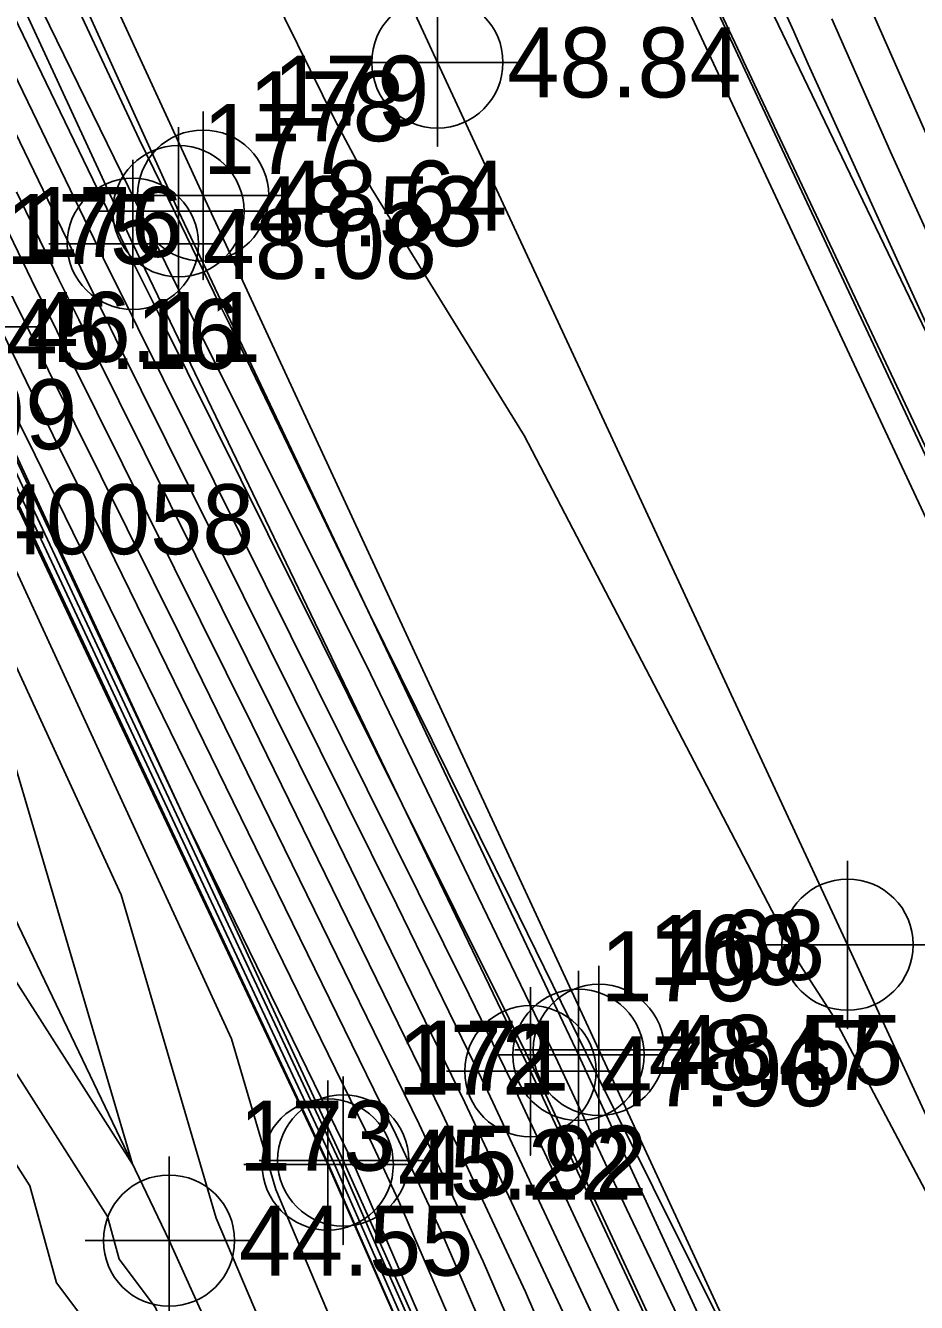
# Model space of a CAD drawing. Extents: x 2090860 to 2091277, y 159470 to 160080.
# Drawn here: x 2091087.9 to 2091119.73, y 159632.66 to 159678.27 of the extents above; entities that cross this region are included whole.
import ezdxf

# ---------------------------------------------------------------- set-up
doc = ezdxf.new("R2010")
doc.units = 0
for name, color, linetype in [('DTM Contours Major', 7, 'Continuous'), ('DTM Contours Minor', 7, 'Continuous'), ('Exist DTM Breakline', 7, 'Continuous'), ('Exist DTM Breakline Cogo Comment', 7, 'Continuous'), ('Exist DTM Breakline Cogo Elevation', 7, 'Continuous'), ('Exist DTM Breakline Cogo Number', 7, 'Continuous'), ('Exist DTM Breakline Cogo Point CELL', 7, 'Continuous'), ('Exist DTM Crownline', 7, 'Continuous'), ('Exist DTM Crownline Cogo Elevation', 7, 'Continuous'), ('Exist DTM Crownline Cogo Point CELL', 7, 'Continuous'), ('Exist Roads EOP', 7, 'Continuous'), ('Exist Roads EOP Cogo Elevation', 7, 'Continuous'), ('Exist Roads EOP Cogo Number', 7, 'Continuous'), ('Exist Roads EOP Cogo Point CELL', 7, 'Continuous'), ('Exist Roads EOT', 7, 'Continuous'), ('Exist Roads EOT Cogo Elevation', 7, 'Continuous'), ('Exist Roads EOT Cogo Number', 7, 'Continuous'), ('Exist Roads EOT Cogo Point CELL', 7, 'Continuous')]:
    doc.layers.add(name, color=color, linetype=linetype)

msp = doc.modelspace()

# ---------------------------------------------------------------- linework, layer by layer
at = {"layer": 'DTM Contours Major'}
for points in [[(2091079.813, 159694.479), (2091091.479, 159670.351), (2091092.674, 159667.942), (2091092.718, 159667.852), (2091101.365, 159650.434), (2091105.185, 159642.793), (2091106.067, 159640.964), (2091111.338, 159629.685), (2091111.718, 159628.889), (2091112.961, 159626.284), (2091124.433, 159601.716), (2091124.607, 159601.347), (2091126.942, 159596.528), (2091128.343, 159593.558), (2091139.93, 159569.539)], [(2091077.176, 159683.472), (2091085.357, 159667.475), (2091085.495, 159667.182), (2091086.555, 159664.923), (2091087.913, 159662.036), (2091093.577, 159649.962), (2091099.498, 159637.849), (2091099.709, 159637.399), (2091104.938, 159625.32), (2091105.136, 159624.896), (2091108.736, 159616.547), (2091117.028, 159597.858), (2091117.244, 159597.435), (2091119.625, 159592.62), (2091130.861, 159569.9)], [(2091082.79, 159680.214), (2091088.287, 159668.846), (2091088.85, 159667.711), (2091089.525, 159666.328), (2091095.999, 159653.287), (2091102.781, 159639.414), (2091105.76, 159633.037), (2091108.329, 159627.103), (2091114.857, 159613.131), (2091120.634, 159599.73), (2091121.876, 159597.167), (2091123.209, 159594.519), (2091129.912, 159580.676)], [(2091163.429, 159579.673), (2091153.599, 159600.613), (2091150.617, 159606.792), (2091148.169, 159612.011), (2091147.459, 159613.481), (2091138.047, 159634.57), (2091135.191, 159640.875), (2091131.528, 159649.079), (2091130.314, 159651.757), (2091121.742, 159670.624), (2091117.989, 159679.115)], [(2091129.857, 159570.34), (2091117.802, 159591.64), (2091117.171, 159592.866), (2091114.927, 159596.852), (2091110.323, 159606.006), (2091102.573, 159624.179), (2091100.334, 159628.452), (2091096.842, 159636.697), (2091095.262, 159642.075), (2091085.023, 159664.299)], [(2091080.029, 159649.409), (2091088.053, 159636.828), (2091089.011, 159633.367), (2091091.931, 159629.479), (2091095.15, 159621.315), (2091096.661, 159619.317), (2091099.104, 159615.886), (2091107.122, 159596.733), (2091107.485, 159593.301), (2091109.226, 159589.679)]]:
    msp.add_lwpolyline(points, dxfattribs=at)
at = {"layer": 'DTM Contours Minor'}
for points in [[(2091080.51, 159698.642), (2091091.966, 159674.206), (2091093.26, 159671.558), (2091094.64, 159668.709), (2091094.706, 159668.575), (2091095.273, 159667.441), (2091100.175, 159657.278), (2091105.245, 159647.055), (2091107.931, 159641.569), (2091110.32, 159636.766), (2091113.678, 159630.044), (2091114.986, 159627.423), (2091125.393, 159610.705), (2091128.86, 159603.992), (2091130.664, 159600.208), (2091131.424, 159598.524), (2091140.273, 159579.961)], [(2091080.273, 159695.626), (2091092.352, 159670.911), (2091092.91, 159669.758), (2091093.68, 159668.217), (2091100.229, 159655.117), (2091106.917, 159641.251), (2091109.366, 159636.01), (2091112.54, 159629.361), (2091122.928, 159607.603), (2091125.409, 159602.289), (2091127.327, 159598.223), (2091127.819, 159597.207), (2091138.555, 159574.438)], [(2091072.913, 159694.755), (2091083.535, 159676.648), (2091087.489, 159668.47), (2091087.894, 159667.653), (2091088.727, 159665.947), (2091093.416, 159656.501), (2091101.96, 159639.023), (2091104.247, 159634.128), (2091107.481, 159626.657), (2091112.427, 159616.072), (2091119.685, 159599.236), (2091120.595, 159597.359), (2091122.273, 159594.024), (2091127.204, 159583.841)], [(2091070.474, 159693.642), (2091081.681, 159673.757), (2091084.964, 159667.339), (2091085.735, 159665.698), (2091086.157, 159664.799), (2091094.809, 159646.403), (2091098.918, 159637.644), (2091102.338, 159629.862), (2091104.449, 159625.11), (2091112.732, 159606.254), (2091116.546, 159597.659), (2091118.37, 159594.073), (2091119.204, 159592.386), (2091123.926, 159582.838)], [(2091073.926, 159690.732), (2091084.279, 159673.082), (2091086.691, 159668.093), (2091086.938, 159667.595), (2091087.929, 159665.566), (2091090.833, 159659.715), (2091101.14, 159638.632), (2091102.735, 159635.218), (2091106.633, 159626.212), (2091109.996, 159619.013), (2091118.736, 159598.741), (2091119.313, 159597.552), (2091121.338, 159593.528), (2091124.496, 159587.006)], [(2091080.558, 159690.913), (2091090.681, 159669.974), (2091091.718, 159667.884), (2091091.92, 159667.471), (2091103.748, 159643.645), (2091105.242, 159640.588), (2091110.299, 159629.767), (2091110.873, 159628.44), (2091122.148, 159604.306), (2091123.481, 159601.214), (2091125.721, 159596.589), (2091126.015, 159596.005), (2091138.036, 159571.181)], [(2091074.923, 159688.329), (2091081.29, 159675.881), (2091085.023, 159669.516), (2091085.893, 159667.717), (2091085.982, 159667.538), (2091087.13, 159665.185), (2091088.251, 159662.929), (2091100.319, 159638.24), (2091101.222, 159636.308), (2091105.785, 159625.766), (2091107.566, 159621.955), (2091117.788, 159598.247), (2091118.031, 159597.744), (2091120.402, 159593.033), (2091121.788, 159590.171)], [(2091092.675, 159687.628), (2091098.961, 159674.873), (2091100.257, 159672.453), (2091101.069, 159671.14), (2091105.715, 159663.627), (2091115.58, 159644.724), (2091116.703, 159642.969), (2091121.642, 159633.637), (2091122.802, 159631.775), (2091129.869, 159618.089), (2091132.718, 159622.878), (2091137.14, 159624.41), (2091135.353, 159628.744), (2091131.259, 159638.725), (2091131.05, 159639.235), (2091130.694, 159640.103), (2091126.571, 159649.248), (2091126.304, 159649.847), (2091125.204, 159652.293), (2091113.546, 159676.999), (2091113.443, 159677.236), (2091111.307, 159681.76)], [(2091081.302, 159687.347), (2091089.883, 159669.598), (2091090.762, 159667.827), (2091091.122, 159667.09), (2091101.165, 159646.859), (2091104.422, 159640.197), (2091108.786, 159630.857), (2091110.025, 159627.994), (2091119.717, 159607.248), (2091122.532, 159600.719), (2091124.44, 159596.782), (2091125.08, 159595.509), (2091135.328, 159574.346)], [(2091082.046, 159683.781), (2091089.085, 159669.222), (2091089.806, 159667.769), (2091090.323, 159666.709), (2091098.582, 159650.073), (2091103.601, 159639.806), (2091107.273, 159631.947), (2091109.177, 159627.548), (2091117.287, 159610.189), (2091121.583, 159600.225), (2091123.158, 159596.974), (2091124.144, 159595.014), (2091132.62, 159577.511)], [(2091160.862, 159578.349), (2091151.097, 159599.184), (2091148.077, 159605.5), (2091147.174, 159607.39), (2091144.949, 159612.13), (2091141.732, 159619.248), (2091132.693, 159639.533), (2091131.752, 159641.619), (2091127.777, 159650.544), (2091122.382, 159662.543), (2091115.863, 159676.89), (2091115.422, 159677.888), (2091115.345, 159678.061), (2091113.296, 159682.58)], [(2091079.429, 159678.614), (2091085.16, 159667.407), (2091085.615, 159666.44), (2091086.356, 159664.861), (2091091.361, 159654.219), (2091099.113, 159637.695), (2091100.516, 159634.501), (2091104.653, 159625.193), (2091108.518, 159616.394), (2091116.787, 159597.759), (2091117.807, 159595.754), (2091119.414, 159592.503), (2091128.512, 159574.108)], [(2091162.131, 159578.985), (2091150.559, 159603.635), (2091149.359, 159606.123), (2091146.488, 159612.24), (2091146.209, 159612.821), (2091135.187, 159637.514), (2091133.962, 159640.22), (2091129.606, 159649.977), (2091129.069, 159651.161), (2091118.802, 159673.757), (2091116.705, 159678.502)], [(2091081.412, 159665.629), (2091076.043, 159666.181), (2091076.463, 159663.189), (2091077.511, 159661.431), (2091076.47, 159657.66), (2091080.049, 159655.898), (2091091.723, 159637.594), (2091087.381, 159652.367), (2091082.453, 159663.064), (2091081.92, 159664.529), (2091081.412, 159665.629)], [(2091132.489, 159565.487), (2091119.34, 159591.568), (2091118.994, 159592.269), (2091118.933, 159592.393), (2091118.041, 159594.145), (2091116.161, 159597.483), (2091115.582, 159598.635), (2091107.01, 159618.735), (2091104.245, 159625.028), (2091104.159, 159625.223), (2091098.723, 159637.593), (2091098.257, 159638.587), (2091085.958, 159664.737)], [(2091127.322, 159571.892), (2091116.525, 159590.966), (2091115.21, 159593.526), (2091113.692, 159596.22), (2091105.065, 159613.377), (2091100.835, 159623.295), (2091096.258, 159632.032), (2091094.714, 159635.676), (2091091.322, 159647.221), (2091083.738, 159663.682)], [(2091080.039, 159652.653), (2091090.83, 159635.734), (2091091.253, 159634.205), (2091092.544, 159632.486), (2091096.783, 159621.732), (2091097.608, 159620.641), (2091098.942, 159618.769), (2091108.415, 159596.14), (2091108.66, 159593.82), (2091110.674, 159589.629)]]:
    msp.add_lwpolyline(points, dxfattribs=at)
at = {"layer": 'Exist DTM Breakline'}
for points in [[(2091196.63, 159502.872), (2091177.33, 159544.144), (2091161.139, 159578.46), (2091145.393, 159612.39), (2091128.083, 159650.689), (2091112.842, 159682.377), (2091098.521, 159713.445), (2091088.424, 159738.261), (2091087.489, 159747.73)], [(2091169.184, 159489.682), (2091149.135, 159531.027), (2091132.914, 159565.727), (2091117.093, 159597.885), (2091099.249, 159637.73), (2091085.443, 159667.505), (2091069.301, 159700.059), (2091060.276, 159722.819), (2091058.458, 159734.195), (2091059.361, 159735), (2091060.617, 159735.809)], [(2091168.326, 159489.347), (2091148.612, 159530.829), (2091132.315, 159565.389), (2091116.339, 159597.574), (2091098.698, 159637.587), (2091084.7, 159667.248), (2091067.163, 159699.242), (2091053.414, 159724.442), (2091052.893, 159730.303), (2091057.39, 159734.945)], [(2091175.557, 159492.591), (2091156.216, 159533.598), (2091139.639, 159569.307), (2091124.335, 159601.659), (2091105.938, 159640.92), (2091091.734, 159670.471), (2091076.451, 159703.516), (2091059.361, 159735)], [(2091163.514, 159486.332), (2091143.762, 159527.932), (2091127.118, 159562.647), (2091111.114, 159594.902), (2091093.029, 159634.868), (2091078.886, 159664.385)]]:
    msp.add_lwpolyline(points, dxfattribs=at)
at = {"layer": 'Exist DTM Breakline Cogo Point CELL'}
for points in [[(2091091.734, 159673.471), (2091091.734, 159667.471), (2091091.734, 159670.471), (2091094.734, 159670.471), (2091088.734, 159670.471)], [(2091085.443, 159670.505), (2091085.443, 159664.505), (2091085.443, 159667.505), (2091088.443, 159667.505), (2091082.443, 159667.505)], [(2091105.938, 159643.92), (2091105.938, 159637.92), (2091105.938, 159640.92), (2091108.938, 159640.92), (2091102.938, 159640.92)], [(2091098.698, 159640.587), (2091098.698, 159634.587), (2091098.698, 159637.587), (2091101.698, 159637.587), (2091095.698, 159637.587)], [(2091099.249, 159640.73), (2091099.249, 159634.73), (2091099.249, 159637.73), (2091102.249, 159637.73), (2091096.249, 159637.73)], [(2091093.029, 159637.868), (2091093.029, 159631.868), (2091093.029, 159634.868), (2091096.029, 159634.868), (2091090.029, 159634.868)]]:
    msp.add_lwpolyline(points, dxfattribs=at)
for centre in [(2091091.734, 159670.471), (2091105.938, 159640.92), (2091099.249, 159637.73), (2091098.698, 159637.587), (2091093.029, 159634.868)]:
    msp.add_circle(centre, 2.344, dxfattribs=at)
at = {"layer": 'Exist DTM Crownline'}
msp.add_lwpolyline([(2091186.231, 159497.374), (2091150.267, 159573.786), (2091135.077, 159606.786), (2091117.269, 159645.439), (2091102.614, 159676.949), (2091088.105, 159708.377), (2091072.916, 159741.265)], dxfattribs=at)
at = {"layer": 'Exist DTM Crownline Cogo Point CELL'}
for points in [[(2091102.614, 159679.949), (2091102.614, 159673.949), (2091102.614, 159676.949), (2091105.614, 159676.949), (2091099.614, 159676.949)], [(2091117.269, 159648.439), (2091117.269, 159642.439), (2091117.269, 159645.439), (2091120.269, 159645.439), (2091114.269, 159645.439)]]:
    msp.add_lwpolyline(points, dxfattribs=at)
for centre in [(2091102.614, 159676.949), (2091117.269, 159645.439)]:
    msp.add_circle(centre, 2.344, dxfattribs=at)
at = {"layer": 'Exist Roads EOP'}
for points in [[(2091195.022, 159502.3), (2091175.816, 159543.301), (2091159.602, 159577.847), (2091143.942, 159611.542), (2091126.198, 159649.797), (2091111.241, 159681.734), (2091096.716, 159712.783), (2091082.116, 159745.373)], [(2091176.987, 159492.996), (2091157.634, 159534.321), (2091140.802, 159570.232), (2091125.679, 159602.447), (2091107.654, 159641.501), (2091093.369, 159671.636), (2091078.486, 159704.356), (2091063.606, 159736.869)]]:
    msp.add_lwpolyline(points, dxfattribs=at)
at = {"layer": 'Exist Roads EOP Cogo Point CELL'}
for points in [[(2091093.369, 159674.636), (2091093.369, 159668.636), (2091093.369, 159671.636), (2091096.369, 159671.636), (2091090.369, 159671.636)], [(2091107.654, 159644.501), (2091107.654, 159638.501), (2091107.654, 159641.501), (2091110.654, 159641.501), (2091104.654, 159641.501)]]:
    msp.add_lwpolyline(points, dxfattribs=at)
for centre in [(2091093.369, 159671.636), (2091107.654, 159641.501)]:
    msp.add_circle(centre, 2.344, dxfattribs=at)
at = {"layer": 'Exist Roads EOT'}
for points in [[(2091194.37, 159502.018), (2091175.119, 159542.803), (2091158.987, 159577.703), (2091143.368, 159611.224), (2091125.349, 159649.375), (2091110.434, 159681.3), (2091096.012, 159712.514), (2091081.141, 159744.981)], [(2091158.031, 159534.505), (2091141.446, 159570.27), (2091126.357, 159602.867), (2091108.385, 159641.68), (2091094.245, 159672.193), (2091079.271, 159704.671), (2091064.194, 159737.108)]]:
    msp.add_lwpolyline(points, dxfattribs=at)
at = {"layer": 'Exist Roads EOT Cogo Point CELL'}
for points in [[(2091102.614, 159679.949), (2091102.614, 159673.949), (2091102.614, 159676.949), (2091099.614, 159676.949), (2091105.614, 159676.949)], [(2091094.245, 159675.193), (2091094.245, 159669.193), (2091094.245, 159672.193), (2091091.245, 159672.193), (2091097.245, 159672.193)], [(2091117.269, 159648.439), (2091117.269, 159642.439), (2091117.269, 159645.439), (2091114.269, 159645.439), (2091120.269, 159645.439)], [(2091108.385, 159644.68), (2091108.385, 159638.68), (2091108.385, 159641.68), (2091105.385, 159641.68), (2091111.385, 159641.68)]]:
    msp.add_lwpolyline(points, dxfattribs=at)
for centre in [(2091102.614, 159676.949), (2091094.245, 159672.193), (2091117.269, 159645.439), (2091108.385, 159641.68)]:
    msp.add_circle(centre, 2.344, dxfattribs=at)

# ---------------------------------------------------------------- texts
at = {"layer": 'Exist DTM Breakline Cogo Comment'}
msp.add_text('*EL40058', height=2.5, dxfattribs=at).set_placement((2091081.386, 159659.385))
at = {"layer": 'Exist DTM Breakline Cogo Elevation'}
for s, p in [('48.08', (2091094.234, 159669.221)), ('46.11', (2091087.943, 159666.255)), ('45.16', (2091087.2, 159665.998)), ('43.99', (2091081.386, 159663.135)), ('47.96', (2091108.438, 159639.67)), ('45.22', (2091101.198, 159636.337)), ('45.92', (2091101.749, 159636.48)), ('44.55', (2091095.529, 159633.618))]:
    msp.add_text(s, height=2.5, dxfattribs=at).set_placement(p)
at = {"layer": 'Exist DTM Breakline Cogo Number'}
for s, p in [('177', (2091094.234, 159672.971)), ('176', (2091087.943, 159670.005)), ('175', (2091087.2, 159669.748)), ('170', (2091108.438, 159643.42)), ('171', (2091101.749, 159640.23)), ('172', (2091101.198, 159640.087)), ('173', (2091095.529, 159637.368))]:
    msp.add_text(s, height=2.5, dxfattribs=at).set_placement(p)
at = {"layer": 'Exist DTM Crownline Cogo Elevation'}
msp.add_text('48.84', height=2.5, dxfattribs=at).set_placement((2091105.114, 159675.699))
at = {"layer": 'Exist Roads EOP Cogo Elevation'}
for s, p in [('48.53', (2091095.869, 159670.386)), ('48.47', (2091110.154, 159640.251))]:
    msp.add_text(s, height=2.5, dxfattribs=at).set_placement(p)
at = {"layer": 'Exist Roads EOP Cogo Number'}
for s, p in [('178', (2091095.869, 159674.136)), ('169', (2091110.154, 159644.001))]:
    msp.add_text(s, height=2.5, dxfattribs=at).set_placement(p)
at = {"layer": 'Exist Roads EOT Cogo Elevation'}
for s, p in [('48.84', (2091105.114, 159675.699)), ('48.64', (2091096.745, 159670.943)), ('48.55', (2091110.885, 159640.43))]:
    msp.add_text(s, height=2.5, dxfattribs=at).set_placement(p)
at = {"layer": 'Exist Roads EOT Cogo Number'}
for s, p in [('179', (2091096.745, 159674.693)), ('168', (2091110.885, 159644.18))]:
    msp.add_text(s, height=2.5, dxfattribs=at).set_placement(p)

doc.saveas('drawing.dxf')
